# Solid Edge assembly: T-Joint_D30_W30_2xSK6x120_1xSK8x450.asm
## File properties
Author: fknapp
Template: iso metric assembly.asm
Last saved by: fknapp
Revision: 7
Application: Solid Edge
Username: fknapp
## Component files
T-Joint_D30_W30.par
SK Knapp Schraube 8x450_ohne_Gewinde_22042020.par
SK Schraube 6x120_ohne_Gewinde.par
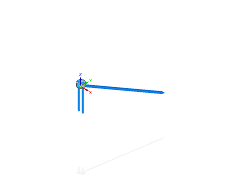
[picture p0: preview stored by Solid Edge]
